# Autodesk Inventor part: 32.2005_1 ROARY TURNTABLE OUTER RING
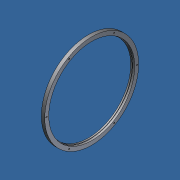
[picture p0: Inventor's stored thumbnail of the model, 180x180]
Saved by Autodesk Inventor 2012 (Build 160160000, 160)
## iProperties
Created: 2017-02
Part Number: 32.2005_1 ROARY TURNTABLE OUTER RING
Material: Aluminum-6061
Document SubType Name: Modeling
Designer: Admin
Density: 2.71 g/cm^3
Mass: 466.815 g
Surface Area: 554.107 cm^2
Volume: 172.257 cm^3
Author: Admin
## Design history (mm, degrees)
sketch "Sketch1"
  geometry: L1 (0, -164)-(-12, -164); L2 (-12, -164)-(-12, -148.2); L3 (-12, -148.2)-(-7.151, -148.2); L4 (-7.151, -148.2)-(-7.151, -150); L5 (-7.151, -150)-(0, -150); L6 (0, -150)-(0, -164); L7 (-14.4, 0)-(2.4, 0) reference; 1 further point
  constraints: 12 end point, 4 parallel, 1 horizontal, 1 perpendicular, 1 vertical alignment
  dimensions: "d0" = 14 distance of L5.end L1.start; "d1" = 12 distance of L1.start L1.end; "d2" = 15.8 distance of L1.end L2.end; "d3" = 164 distance from line of point (0, 0) L1
revolve "Revolution1" sketch "Sketch1" stored, may be unused: angle "d4" = 90 deg
sketch "Sketch2"
  geometry: C1 r 148.2 at (0, 0) reference; 1 further point
  constraints: 1 vertical alignment
  dimensions: "d5" = 157.5 distance of point (0, 157.5) C1.centre
hole "Hole1" sketch "Sketch2" at (0, 157.5) diameter "d6" = 4.917; stored, may be unused: countersink angle "d10" = 90 deg, drill point angle "d12" = 118 deg; dims "d7" = 12, "d8" = 4, "d9" = 2, "d11" = 8
pattern_circular "Circular Pattern1" dims angle "d14" = 360 deg
body "Solid1"
